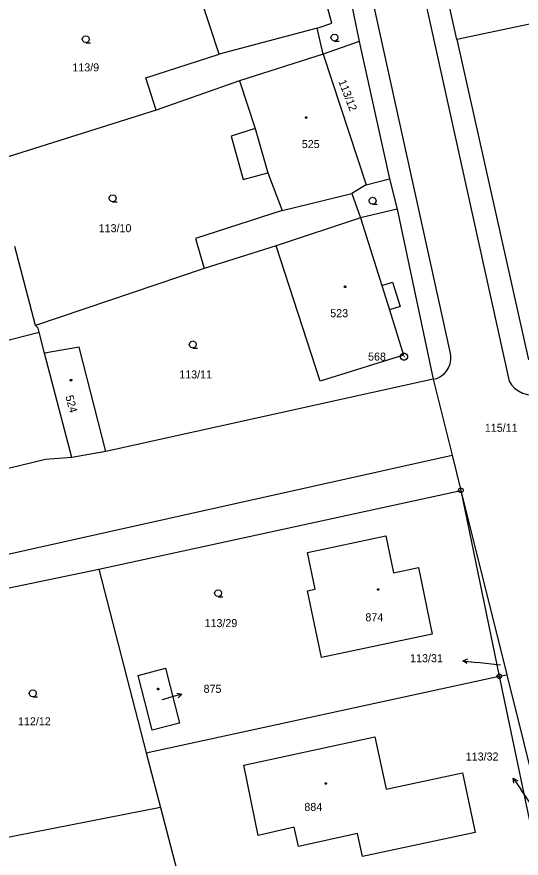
# Model space of a CAD drawing. Extents: x -757994 to -755874, y -1047691 to -1046119.
# Drawn here: x -756398.3 to -756344.8, y -1047042.4 to -1046953.1 of the extents above; entities that cross this region are included whole.
import ezdxf

# ---------------------------------------------------------------- set-up
doc = ezdxf.new("R2010")
doc.units = 0
doc.layers.add('katastrální mapa', color=7, linetype='Continuous')

msp = doc.modelspace()

# ---------------------------------------------------------------- linework, layer by layer
at = {"layer": 'katastrální mapa'}
for p, q in [((-756352.31, -1046988.69), (-756374.35, -1046888.59)), ((-756368.81, -1046888.76), (-756346.03, -1046991.81)), ((-756351.61, -1046955.54), (-756357.39, -1046928.78)), ((-756365.56, -1046938.21), (-756361.96, -1046955.74)), ((-756376.83, -1046957.1), (-756381.41, -1046943.28)), ((-756325.22, -1046949.93), (-756351.61, -1046955.54)), ((-756364.88, -1046953.79), (-756365.76, -1046950.54)), ((-756366.44, -1046954.34), (-756376.83, -1046957.1)), ((-756366.44, -1046954.34), (-756364.88, -1046953.79)), ((-756365.81, -1046957.11), (-756366.44, -1046954.34)), ((-756361.96, -1046955.74), (-756365.81, -1046957.11)), ((-756361.96, -1046955.74), (-756358.74, -1046970.33)), ((-756351.61, -1046955.54), (-756343.98, -1046989.54)), ((-756384.63, -1046959.62), (-756376.83, -1046957.1)), ((-756365.81, -1046957.11), (-756374.68, -1046959.92)), ((-756365.81, -1046957.11), (-756361.22, -1046970.97)), ((-756383.52, -1046963.05), (-756384.63, -1046959.62)), ((-756374.68, -1046959.92), (-756383.52, -1046963.05)), ((-756374.68, -1046959.92), (-756373.02, -1046964.99)), ((-756383.52, -1046963.05), (-756400.69, -1046968.43)), ((-756373.02, -1046964.99), (-756375.56, -1046965.79)), ((-756373.02, -1046964.99), (-756371.68, -1046969.68)), ((-756375.56, -1046965.79), (-756374.28, -1046970.39)), ((-756374.28, -1046970.39), (-756371.68, -1046969.68)), ((-756371.68, -1046969.68), (-756370.16, -1046973.7)), ((-756361.22, -1046970.97), (-756358.74, -1046970.33)), ((-756358.74, -1046970.33), (-756357.93, -1046973.54)), ((-756361.22, -1046970.97), (-756362.76, -1046971.87)), ((-756370.16, -1046973.7), (-756362.76, -1046971.87)), ((-756362.76, -1046971.87), (-756361.83, -1046974.46)), ((-756370.16, -1046973.7), (-756379.36, -1046976.65)), ((-756357.93, -1046973.54), (-756361.83, -1046974.46)), ((-756357.93, -1046973.54), (-756354.12, -1046991.6)), ((-756361.83, -1046974.46), (-756370.79, -1046977.43)), ((-756361.83, -1046974.46), (-756359.57, -1046981.65)), ((-756379.36, -1046976.65), (-756378.43, -1046979.83)), ((-756396.32, -1046985.89), (-756398.53, -1046977.5)), ((-756370.79, -1046977.43), (-756378.43, -1046979.83)), ((-756366.11, -1046991.81), (-756370.79, -1046977.43)), ((-756378.43, -1046979.83), (-756396.32, -1046985.89)), ((-756359.57, -1046981.65), (-756358.43, -1046981.29)), ((-756359.57, -1046981.65), (-756358.76, -1046984.22)), ((-756358.43, -1046981.29), (-756357.62, -1046983.86)), ((-756357.62, -1046983.86), (-756358.76, -1046984.22)), ((-756358.76, -1046984.22), (-756357.25, -1046989.04)), ((-756396.06, -1046986.19), (-756396.32, -1046985.89)), ((-756395.95, -1046986.6), (-756396.06, -1046986.19)), ((-756400.25, -1046987.7), (-756395.95, -1046986.6)), ((-756395.38, -1046988.84), (-756395.95, -1046986.6)), ((-756391.7, -1046988.19), (-756395.38, -1046988.84)), ((-756388.85, -1046999.25), (-756391.7, -1046988.19)), ((-756392.47, -1046999.91), (-756395.38, -1046988.84)), ((-756357.25, -1046989.04), (-756366.11, -1046991.81)), ((-756357.225, -1046989.19), (-756357.175, -1046989.19)), ((-756354.12, -1046991.6), (-756388.85, -1046999.25)), ((-756354.12, -1046991.6), (-756352.11, -1046999.66)), ((-756392.47, -1046999.91), (-756395.28, -1047000.1)), ((-756388.85, -1046999.25), (-756392.47, -1046999.91)), ((-756389.74, -1047008.05), (-756352.11, -1046999.66)), ((-756352.11, -1046999.66), (-756351.18, -1047003.39)), ((-756395.28, -1047000.1), (-756412.16, -1047004.18)), ((-756389.6, -1047011.74), (-756351.18, -1047003.39)), ((-756351.24, -1047003.39), (-756351.12, -1047003.39)), ((-756351.18, -1047003.39), (-756347.09, -1047023.12)), ((-756351.18, -1047003.39), (-756346.31, -1047022.95)), ((-756431.3, -1047017.32), (-756389.74, -1047008.05)), ((-756367.47, -1047009.97), (-756359.15, -1047008.21)), ((-756359.15, -1047008.21), (-756358.33, -1047012.13)), ((-756366.66, -1047013.87), (-756367.47, -1047009.97)), ((-756408.88, -1047015.73), (-756389.6, -1047011.74)), ((-756389.6, -1047011.74), (-756384.57, -1047031.26)), ((-756358.33, -1047012.13), (-756355.68, -1047011.58)), ((-756355.68, -1047011.58), (-756354.21, -1047018.64)), ((-756367.44, -1047014.04), (-756366.66, -1047013.87)), ((-756365.96, -1047021.11), (-756367.44, -1047014.04)), ((-756354.21, -1047018.64), (-756365.96, -1047021.11)), ((-756385.44, -1047023.04), (-756382.55, -1047022.27)), ((-756382.55, -1047022.27), (-756381.05, -1047028.11)), ((-756350.96, -1047021.464), (-756349.47, -1047021.64)), ((-756346.98, -1047021.93), (-756349.47, -1047021.64)), ((-756383.94, -1047028.85), (-756385.44, -1047023.04)), ((-756384.57, -1047031.26), (-756347.09, -1047023.12)), ((-756347.15, -1047023.12), (-756347.03, -1047023.12)), ((-756347.09, -1047023.12), (-756346.31, -1047022.95)), ((-756347.09, -1047023.12), (-756342.39, -1047045.7)), ((-756346.31, -1047022.95), (-756340.74, -1047045.34)), ((-756382.87, -1047025.6), (-756382.23, -1047025.42)), ((-756380.782, -1047025.029), (-756382.23, -1047025.42)), ((-756381.05, -1047028.11), (-756383.94, -1047028.85)), ((-756384.57, -1047031.26), (-756383.08, -1047037.05)), ((-756345.607, -1047033.925), (-756344.77, -1047035.17)), ((-756343.72, -1047036.73), (-756344.77, -1047035.17)), ((-756383.08, -1047037.05), (-756400.59, -1047040.49)), ((-756383.08, -1047037.05), (-756378.72, -1047053.6))]:
    msp.add_line(p, q, dxfattribs=at)
for points in [[(-756390.99, -1046955.87), (-756391.18, -1046955.82), (-756391.315, -1046955.685), (-756391.365, -1046955.5), (-756391.315, -1046955.315), (-756391.18, -1046955.18), (-756390.995, -1046955.13), (-756390.81, -1046955.18), (-756390.675, -1046955.315), (-756390.625, -1046955.505), (-756390.675, -1046955.695), (-756390.81, -1046955.83), (-756391, -1046955.88), (-756390.5, -1046955.88)], [(-756364.59, -1046955.7), (-756364.78, -1046955.65), (-756364.915, -1046955.515), (-756364.965, -1046955.33), (-756364.915, -1046955.145), (-756364.78, -1046955.01), (-756364.595, -1046954.96), (-756364.41, -1046955.01), (-756364.275, -1046955.145), (-756364.225, -1046955.335), (-756364.275, -1046955.525), (-756364.41, -1046955.66), (-756364.6, -1046955.71), (-756364.1, -1046955.71)], [(-756388.14, -1046972.75), (-756388.33, -1046972.7), (-756388.465, -1046972.565), (-756388.515, -1046972.38), (-756388.465, -1046972.195), (-756388.33, -1046972.06), (-756388.145, -1046972.01), (-756387.96, -1046972.06), (-756387.825, -1046972.195), (-756387.775, -1046972.385), (-756387.825, -1046972.575), (-756387.96, -1046972.71), (-756388.15, -1046972.76), (-756387.65, -1046972.76)], [(-756360.54, -1046973.02), (-756360.73, -1046972.97), (-756360.865, -1046972.835), (-756360.915, -1046972.65), (-756360.865, -1046972.465), (-756360.73, -1046972.33), (-756360.545, -1046972.28), (-756360.36, -1046972.33), (-756360.225, -1046972.465), (-756360.175, -1046972.655), (-756360.225, -1046972.845), (-756360.36, -1046972.98), (-756360.55, -1046973.03), (-756360.05, -1046973.03)], [(-756379.63, -1046988.27), (-756379.82, -1046988.22), (-756379.955, -1046988.085), (-756380.005, -1046987.9), (-756379.955, -1046987.715), (-756379.82, -1046987.58), (-756379.635, -1046987.53), (-756379.45, -1046987.58), (-756379.315, -1046987.715), (-756379.265, -1046987.905), (-756379.315, -1046988.095), (-756379.45, -1046988.23), (-756379.64, -1046988.28), (-756379.14, -1046988.28)], [(-756354.12, -1046991.6), (-756353.727, -1046991.498), (-756353.319, -1046991.299), (-756352.959, -1046991.025), (-756352.69, -1046990.72), (-756352.471, -1046990.382), (-756352.307, -1046989.968), (-756352.225, -1046989.53), (-756352.228, -1046989.084), (-756352.31, -1046988.69)], [(-756346.03, -1046991.81), (-756345.783, -1046992.195), (-756345.429, -1046992.57), (-756345.06, -1046992.84), (-756344.641, -1046993.065), (-756344.113, -1046993.227), (-756343.563, -1046993.284), (-756343.09, -1046993.24)], [(-756376.94, -1047014.67), (-756377.13, -1047014.62), (-756377.265, -1047014.485), (-756377.315, -1047014.3), (-756377.265, -1047014.115), (-756377.13, -1047013.98), (-756376.945, -1047013.93), (-756376.76, -1047013.98), (-756376.625, -1047014.115), (-756376.575, -1047014.305), (-756376.625, -1047014.495), (-756376.76, -1047014.63), (-756376.95, -1047014.68), (-756376.45, -1047014.68)], [(-756350.492, -1047021.771), (-756350.96, -1047021.464), (-756350.434, -1047021.274)], [(-756396.62, -1047025.3), (-756396.81, -1047025.25), (-756396.945, -1047025.115), (-756396.995, -1047024.93), (-756396.945, -1047024.745), (-756396.81, -1047024.61), (-756396.625, -1047024.56), (-756396.44, -1047024.61), (-756396.305, -1047024.745), (-756396.255, -1047024.935), (-756396.305, -1047025.125), (-756396.44, -1047025.26), (-756396.63, -1047025.31), (-756396.13, -1047025.31)], [(-756381.33, -1047024.918), (-756380.782, -1047025.029), (-756381.199, -1047025.401)], [(-756345.535, -1047034.48), (-756345.607, -1047033.925), (-756345.121, -1047034.201)]]:
    msp.add_lwpolyline(points, dxfattribs=at)
for points in [[(-756367.6, -1046963.735), (-756367.55, -1046963.745), (-756367.525, -1046963.79), (-756367.515, -1046963.82), (-756367.525, -1046963.865), (-756367.565, -1046963.9), (-756367.6, -1046963.905), (-756367.645, -1046963.89), (-756367.675, -1046963.86), (-756367.685, -1046963.82), (-756367.675, -1046963.775), (-756367.635, -1046963.74)], [(-756363.47, -1046981.685), (-756363.42, -1046981.695), (-756363.395, -1046981.74), (-756363.385, -1046981.77), (-756363.395, -1046981.815), (-756363.435, -1046981.85), (-756363.47, -1046981.855), (-756363.515, -1046981.84), (-756363.545, -1046981.81), (-756363.555, -1046981.77), (-756363.545, -1046981.725), (-756363.505, -1046981.69)], [(-756357.105, -1046988.83), (-756356.935, -1046988.925), (-756356.84, -1046989.095), (-756356.84, -1046989.29), (-756356.935, -1046989.46), (-756357.105, -1046989.555), (-756357.3, -1046989.555), (-756357.47, -1046989.46), (-756357.565, -1046989.29), (-756357.565, -1046989.095), (-756357.47, -1046988.925), (-756357.3, -1046988.83)], [(-756392.57, -1046991.615), (-756392.52, -1046991.625), (-756392.495, -1046991.67), (-756392.485, -1046991.7), (-756392.495, -1046991.745), (-756392.535, -1046991.78), (-756392.57, -1046991.785), (-756392.615, -1046991.77), (-756392.645, -1046991.74), (-756392.655, -1046991.7), (-756392.645, -1046991.655), (-756392.605, -1046991.62)], [(-756351.105, -1047003.15), (-756350.98, -1047003.24), (-756350.93, -1047003.385), (-756350.98, -1047003.53), (-756351.105, -1047003.62), (-756351.26, -1047003.62), (-756351.385, -1047003.53), (-756351.435, -1047003.385), (-756351.385, -1047003.24), (-756351.26, -1047003.15)], [(-756359.95, -1047013.825), (-756359.9, -1047013.835), (-756359.875, -1047013.88), (-756359.865, -1047013.91), (-756359.875, -1047013.955), (-756359.915, -1047013.99), (-756359.95, -1047013.995), (-756359.995, -1047013.98), (-756360.025, -1047013.95), (-756360.035, -1047013.91), (-756360.025, -1047013.865), (-756359.985, -1047013.83)], [(-756347.015, -1047022.88), (-756346.89, -1047022.97), (-756346.84, -1047023.115), (-756346.89, -1047023.26), (-756347.015, -1047023.35), (-756347.17, -1047023.35), (-756347.295, -1047023.26), (-756347.345, -1047023.115), (-756347.295, -1047022.97), (-756347.17, -1047022.88)], [(-756383.32, -1047024.385), (-756383.27, -1047024.395), (-756383.245, -1047024.44), (-756383.235, -1047024.47), (-756383.245, -1047024.515), (-756383.285, -1047024.55), (-756383.32, -1047024.555), (-756383.365, -1047024.54), (-756383.395, -1047024.51), (-756383.405, -1047024.47), (-756383.395, -1047024.425), (-756383.355, -1047024.39)], [(-756374.21, -1047032.54), (-756360.32, -1047029.56), (-756359.11, -1047035.11), (-756351, -1047033.35), (-756349.64, -1047039.69), (-756361.62, -1047042.26), (-756362.15, -1047039.82), (-756368.41, -1047041.19), (-756368.87, -1047039.15), (-756372.7, -1047040.01)], [(-756365.5, -1047034.415), (-756365.45, -1047034.425), (-756365.425, -1047034.47), (-756365.415, -1047034.5), (-756365.425, -1047034.545), (-756365.465, -1047034.58), (-756365.5, -1047034.585), (-756365.545, -1047034.57), (-756365.575, -1047034.54), (-756365.585, -1047034.5), (-756365.575, -1047034.455), (-756365.535, -1047034.42)]]:
    msp.add_lwpolyline(points, close=True, dxfattribs=at)

# ---------------------------------------------------------------- texts
for s, height, p in [('113/9', 0.85, (-756392.422, -1046958.92)), ('525', 0.85, (-756368.061, -1046967.06)), ('113/10', 0.85, (-756389.626, -1046975.99)), ('523', 0.85, (-756365.041, -1046985.01)), ('568', 0.85, (-756361.027, -1046989.615)), ('113/11', 0.85, (-756381.069, -1046991.51)), ('115/11', 0.85, (-756348.629, -1046997.17)), ('874', 0.85, (-756361.31, -1047017.28)), ('113/29', 0.85, (-756378.384, -1047017.9)), ('113/31', 0.85, (-756356.561, -1047021.625)), ('113/31', 0.05, (-756346.968, -1047021.93)), ('875', 0.85, (-756378.491, -1047024.875)), ('875', 0.05, (-756382.863, -1047025.6)), ('112/12', 0.85, (-756398.193, -1047028.33)), ('113/32', 0.85, (-756350.653, -1047032.06)), ('884', 0.85, (-756367.791, -1047037.41))]:
    msp.add_text(s, height=height, dxfattribs=at).set_placement(p)
for s, rotation, p in [('113/12', 291.23445, (-756364.197, -1046959.99)), ('524', 285.33298, (-756393.174, -1046993.41))]:
    msp.add_text(s, height=0.85, rotation=rotation, dxfattribs=at).set_placement(p)

doc.saveas('drawing.dxf')
